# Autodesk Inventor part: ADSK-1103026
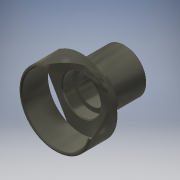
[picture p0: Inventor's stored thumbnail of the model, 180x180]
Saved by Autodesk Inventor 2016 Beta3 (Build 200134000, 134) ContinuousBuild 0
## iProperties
Shininess: 41.0
Length Units: 11272
Angle Units: 11279
Time Units: 11290
Mass Units: 11286
Length Display Precision: 4
Angle Display Precision: 2
Compacted: True
Created: 2000-08
Part Number: ADSK-1103026
Document SubType Name: Modeling
Description: 24 TOOTH CLUTCH GEAR
Mass: 3.13134 g
Surface Area: 23.3651 cm^2
Volume: 1.15548 cm^3
Density: 2.71 g/cm^3
Material: Aluminum-6061
Appearance: Gunmetal
Density: 0.0
Volumn: 0.0
Area: 0.0
PropertySet Name: Model Information
Control State: 0
Master: False
Checked Out: False
Author: Autodesk, Inc.
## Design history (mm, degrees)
node "Extrusion1" dims "d1" = 8.4328, "d2" = 0
  sketch "Sketch3"
    geometry: C1 r 10.477 at (-1.128, -0.122)
    constraints: 1 centre point
    dimensions: "d0" = 20.955 diameter of C1
node "Shell1" dims "d3" = 0.8128
node "Extrusion2" dims "d5" = 11.8872, "d6" = 0
  sketch "Sketch4"
    geometry: C1 r 10.477 at (0, 0) reference; C2 r 6.35 at (0, 0)
    constraints: 1 centre point, 1 concentric
    dimensions: "d4" = 12.7 diameter of C2
node "Extrusion3" dims "d8" = 0.8128, "d9" = 0
  sketch "Sketch5"
    geometry: L1 (-6.839, 7.938)-(6.839, 7.938); A1 r 10.477 centre (0, 0) between (-6.839, 7.938) and (6.839, 7.938) reference
    constraints: 2 end point, 2 point on circle, 1 horizontal
    dimensions: "d7" = 2.54 distance edge to line of A1 L1
node "Circular Pattern1" dims "d10" = 30, "d12" = 360 deg
node "Extrusion4" dims "d14" = 2.99974, "d15" = 0
  sketch "Sketch6"
    geometry: C1 r 6.35 at (0, 0) reference; C2 r 5.524 at (0, 0)
    constraints: 1 centre point, 1 coincident
    dimensions: "d13" = 11.049 diameter of C2
node "Extrusion5" dims "d16" = 2.99974, "d17" = 0
  sketch "Sketch7"
    geometry: C1 r 5.524 at (5.514, -7.938) reference
node "Extrusion6" dims "d19" = 2.54, "d20" = 0
  sketch "Sketch8"
    geometry: C1 r 5.524 at (0, 0) reference; C2 r 4.255 at (0, 0)
    constraints: 1 centre point, 1 coincident
    dimensions: "d18" = 1.27 radial gap between concentric circles of C1 C2
node "Chamfer1" dims "d21" = 0.254, "d22" = 0.254, "d23" = 45 deg
body "Solid1"
